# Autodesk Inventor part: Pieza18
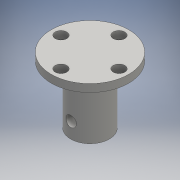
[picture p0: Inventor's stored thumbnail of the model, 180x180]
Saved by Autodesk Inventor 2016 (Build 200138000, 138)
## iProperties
Created: 2016-06
Part Number: Pieza18
Material: Genérico
Document SubType Name: Modeling
Designer: adm
Density: 1 g/cm^3
Appearance: Valor por defecto
Author: adm
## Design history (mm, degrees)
sketch "Boceto1"
  geometry: C1 r 10 at (0, 0); 1 further point
  constraints: 1 centre point, 1 coincident
  dimensions: "d0" = 20 diameter of C1
extrude "Extrusión1" new body sketch "Boceto1" distance "d1" = 2; taper "d2" = 0 deg
sketch "Boceto2"
  geometry: C1 r 5 at (0, 0); 1 further point
  constraints: 1 centre point, 1 coincident
extrude "Extrusión2" join sketch "Boceto2" distance "d3" = 15; taper "d4" = 0 deg
sketch "Boceto3"
  geometry: L1 (-1.918, 1.9)-(1.918, 1.9); L2 (1.918, -1.9)-(-1.918, -1.9); A1 r 2.7 centre (0, 0) between (1.918, -1.9) and (1.918, 1.9); A2 r 2.7 centre (0, 0) between (-1.918, 1.9) and (-1.918, -1.9); 1 further point
  constraints: 4 end point, 4 point on circle, 2 centre point, 2 horizontal, 1 coincident
  dimensions: "d6" = 3.8 distance between parallel lines of L1 L2; "d7" = 1.9 distance from line of L1 point (0, 0)
extrude "Extrusión3" cut sketch "Boceto3" distance "d8" = 10; taper "d9" = 0 deg
sketch "Boceto4"
  geometry: C1 r 1.5 at (7.5, 0); C2 r 10 at (0, 0) reference; C3 r 1.5 at (0, 7.5); C4 r 1.5 at (-7.5, 0); C5 r 1.5 at (0, -7.5); 1 further point
  constraints: 4 centre point, 9 other
  dimensions: "d10" = 3 diameter of C1; "d11" = 7.5 distance of C1.centre point (0, 0); "d14" = 360 deg dimension on point (0, 0) C1.centre (derived)
extrude "Extrusión4" cut sketch "Boceto4" distance "d16" = 10; taper "d17" = 0 deg
node "Plano de trabajo1"
sketch "Boceto5"
  geometry: L1 (-5, -15)-(5, -15) reference; C1 r 1.35 at (0, -11); 1 further point
  constraints: 1 centre point
  dimensions: "d19" = 2.7 diameter of C1; "d20" = 4 distance from line of L1 C1.centre
extrude "Extrusión5" cut sketch "Boceto5" distance "d21" = 6; taper "d22" = 0 deg
node "Sólido1"
other parameters: "d5" = 5.4, "d18" = -5
